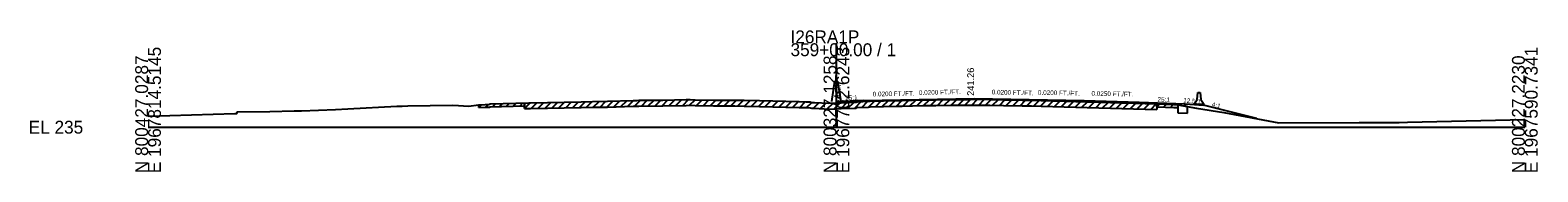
# Model space of a CAD drawing. Extents: x -26 to 304, y -10 to 7527.
# Drawn here: x -25.7 to 302.8, y 4490.3 to 4521.1 of the extents above; entities that cross this region are included whole.
import ezdxf

# ---------------------------------------------------------------- set-up
doc = ezdxf.new("R2010")
doc.units = 0
for name, color, linetype in [('Default', 7, 'Continuous'), ('RD_GPK_XS_Cell', 7, 'Continuous'), ('RD_XS_Base', 7, 'Continuous'), ('RD_XS_Box', 7, 'Continuous'), ('RD_XS_EarthShd', 7, 'Continuous'), ('RD_XS_ExGround', 7, 'Continuous'), ('RD_XS_ExPaveRet', 7, 'Continuous'), ('RD_XS_Misc_Line', 7, 'Continuous'), ('RD_XS_Pave', 7, 'Continuous'), ('RD_XS_PaveShd', 7, 'Continuous'), ('RD_XS_TX_Elev_EX', 7, 'Continuous'), ('RD_XS_TX_Elev_PR', 7, 'Continuous'), ('RD_XS_TX_Misc', 7, 'Continuous'), ('RD_XS_TX_MkPT', 7, 'Continuous'), ('RD_XS_TX_Profile', 7, 'Continuous'), ('RD_XS_TX_Station', 7, 'Continuous')]:
    doc.layers.add(name, color=color, linetype=linetype)

msp = doc.modelspace()

# ---------------------------------------------------------------- linework, layer by layer
at = {"layer": 'Default'}
for p, q in [((228.58, 4506), (228.75, 4507.58)), ((228.75, 4507.58), (229.25, 4507.58)), ((229.25, 4507.58), (229.42, 4506)), ((228, 4505.17), (228.58, 4506)), ((228, 4504.92), (228, 4505.17)), ((230, 4504.92), (228, 4504.92)), ((229.42, 4506), (230, 4505.17)), ((230, 4505.17), (230, 4504.92))]:
    msp.add_line(p, q, dxfattribs=at)
at = {"layer": 'RD_GPK_XS_Cell'}
for p, q in [((150, 4500), (150, 4518.25)), ((0, 4500), (150, 4500)), ((150, 4500), (300, 4500))]:
    msp.add_line(p, q, dxfattribs=at)
at = {"layer": 'RD_XS_Base'}
for p, q in [((150, 4505.27), (150, 4505.54)), ((226, 4504.52), (226, 4505.08)), ((226.5, 4504.5), (226, 4504.52)), ((226.5, 4503.02), (226.5, 4504.5)), ((224.41, 4503.1), (226.5, 4503.02))]:
    msp.add_line(p, q, dxfattribs=at)
at = {"layer": 'RD_XS_Box'}
msp.add_line((241.6, 4501.86), (230, 4504.76), dxfattribs=at)
at = {"layer": 'RD_XS_EarthShd'}
for p, q in [((149, 4505.56), (149.67, 4510.04)), ((150, 4510.04), (149.67, 4510.04)), ((150, 4510.04), (150.33, 4510.04)), ((151, 4505.56), (150.33, 4510.04)), ((226, 4505.08), (230, 4504.76))]:
    msp.add_line(p, q, dxfattribs=at)
at = {"layer": 'RD_XS_ExGround'}
msp.add_lwpolyline([(0, 4502.43), (18.88, 4503), (19.37, 4503.01), (19.47, 4503.31), (26.5, 4503.43), (31.84, 4503.58), (33.4, 4503.57), (40.81, 4503.82), (43.56, 4504), (54.21, 4504.56), (55.36, 4504.61), (56.58, 4504.64), (66.31, 4504.81), (67.67, 4504.71), (69.84, 4504.58), (72.06, 4504.89), (73.48, 4504.96), (74.38, 4505.01), (74.52, 4505.06), (82.97, 4505.32), (83.3, 4505.33), (94.35, 4505.54), (96.86, 4505.58), (100.1, 4505.64), (105.7, 4505.82), (106.5, 4505.84), (106.96, 4505.85), (112.14, 4505.91), (117.28, 4506), (118.14, 4506.01), (119.2, 4505.99), (123.19, 4505.91), (127.87, 4505.88), (129.87, 4505.86), (133.25, 4505.78), (141.89, 4505.56), (143.42, 4505.52), (144.26, 4505.49), (144.55, 4505.4), (145.25, 4505.39), (148.36, 4505.21), (150, 4505.27), (151.03, 4505.31), (154.33, 4505.42), (154.55, 4505.52), (157.02, 4505.64), (157.34, 4505.66), (163.19, 4505.8), (164.33, 4505.83), (168.79, 4505.96), (171.67, 4505.99), (174.88, 4506.03), (178.97, 4506.06), (181.06, 4506.08), (183.41, 4506.03), (186.38, 4505.97), (190.46, 4505.91), (192.54, 4505.88), (194.6, 4505.82), (204.6, 4505.55), (217.3, 4505.17), (223.52, 4504.91), (224.41, 4504.88), (228.48, 4504.14), (234.42, 4503.19), (246.39, 4500.97), (263.88, 4501), (272.65, 4501.01), (274.43, 4501.08), (300, 4501.71)], dxfattribs=at)
at = {"layer": 'RD_XS_ExPaveRet'}
for p, q in [((72.06, 4504.27), (72.06, 4504.89)), ((72.06, 4504.27), (73.48, 4504.34)), ((73.48, 4504.34), (74.38, 4504.38)), ((74.38, 4504.38), (74.52, 4504.43)), ((74.52, 4504.43), (82, 4504.67)), ((82, 4504.04), (82, 4505.29)), ((82, 4505.29), (82, 4504.67)), ((83.3, 4504.08), (94.35, 4504.29)), ((94.35, 4504.29), (96.86, 4504.33)), ((96.86, 4504.33), (100.1, 4504.39)), ((100.1, 4504.39), (105.7, 4504.57)), ((105.7, 4504.57), (106.5, 4504.59)), ((106.5, 4504.59), (106.96, 4504.6)), ((106.96, 4504.6), (112.14, 4504.66)), ((112.14, 4504.66), (117.28, 4504.75)), ((117.28, 4504.75), (118.14, 4504.76)), ((118.14, 4504.76), (119.2, 4504.74)), ((119.2, 4504.74), (123.19, 4504.66)), ((123.19, 4504.66), (127.87, 4504.63)), ((127.87, 4504.63), (129.87, 4504.61)), ((129.87, 4504.61), (133.25, 4504.53)), ((133.25, 4504.53), (141.89, 4504.31)), ((141.89, 4504.31), (143.42, 4504.27)), ((143.42, 4504.27), (144.26, 4504.24)), ((144.26, 4504.24), (144.55, 4504.15)), ((154.33, 4504.17), (154.55, 4504.27)), ((154.55, 4504.27), (157.02, 4504.39)), ((157.02, 4504.39), (157.34, 4504.41)), ((157.34, 4504.41), (163.19, 4504.55)), ((163.19, 4504.55), (164.33, 4504.58)), ((164.33, 4504.58), (168.79, 4504.71)), ((168.79, 4504.71), (171.67, 4504.74)), ((171.67, 4504.74), (174.88, 4504.78)), ((174.88, 4504.78), (178.97, 4504.81)), ((178.97, 4504.81), (181.06, 4504.83)), ((181.06, 4504.83), (183.41, 4504.78)), ((183.41, 4504.78), (186.38, 4504.72)), ((186.38, 4504.72), (190.46, 4504.66)), ((190.46, 4504.66), (192.54, 4504.63)), ((192.54, 4504.63), (194.6, 4504.57)), ((194.6, 4504.57), (204.6, 4504.3)), ((204.6, 4504.3), (217.3, 4503.92)), ((219.79, 4505.07), (219.79, 4503.82)), ((219.79, 4504.44), (219.79, 4505.07)), ((219.79, 4504.44), (223.52, 4504.29)), ((223.52, 4504.29), (224.41, 4504.26)), ((224.41, 4504.88), (224.41, 4504.26)), ((82, 4504.04), (82.97, 4504.07)), ((82.97, 4504.07), (83.3, 4504.08)), ((144.55, 4504.15), (145.25, 4504.14)), ((145.25, 4504.14), (148.36, 4503.96)), ((148.36, 4503.96), (150, 4504.02)), ((150, 4504.02), (151.03, 4504.06)), ((151.03, 4504.06), (154.33, 4504.17)), ((217.3, 4503.92), (219.79, 4503.82))]:
    msp.add_line(p, q, dxfattribs=at)
at = {"layer": 'RD_XS_Misc_Line'}
for p, q in [((72.06, 4504.27), (72.72, 4504.93)), ((73.56, 4504.34), (74.22, 4505)), ((75.06, 4504.45), (75.7, 4505.1)), ((76.56, 4504.5), (77.2, 4505.14)), ((78.06, 4504.54), (78.7, 4505.19)), ((79.56, 4504.59), (80.2, 4505.24)), ((81.06, 4504.64), (81.7, 4505.28)), ((82, 4504.04), (83.29, 4505.33)), ((83.5, 4504.08), (84.77, 4505.36)), ((85, 4504.11), (86.27, 4505.38)), ((86.5, 4504.14), (87.77, 4505.41)), ((88, 4504.17), (89.27, 4505.44)), ((89.5, 4504.2), (90.77, 4505.47)), ((91, 4504.22), (92.27, 4505.5)), ((92.5, 4504.25), (93.77, 4505.53)), ((94, 4504.28), (95.27, 4505.55)), ((95.5, 4504.31), (96.77, 4505.58)), ((97, 4504.34), (98.27, 4505.61)), ((98.5, 4504.36), (99.77, 4505.64)), ((100, 4504.39), (101.29, 4505.68)), ((101.5, 4504.43), (102.79, 4505.73)), ((103, 4504.48), (104.29, 4505.77)), ((104.5, 4504.53), (105.79, 4505.82)), ((106, 4504.58), (107.28, 4505.85)), ((107.5, 4504.6), (108.76, 4505.87)), ((109, 4504.62), (110.26, 4505.89)), ((110.5, 4504.64), (111.76, 4505.9)), ((112, 4504.65), (113.27, 4505.93)), ((113.5, 4504.68), (114.77, 4505.95)), ((115, 4504.71), (116.27, 4505.98)), ((116.5, 4504.74), (117.77, 4506.01)), ((118, 4504.76), (119.23, 4505.99)), ((119.5, 4504.73), (120.73, 4505.96)), ((121, 4504.7), (122.23, 4505.93)), ((122.5, 4504.67), (123.73, 4505.91)), ((124, 4504.65), (125.24, 4505.89)), ((125.5, 4504.64), (126.74, 4505.88)), ((127, 4504.63), (128.24, 4505.87)), ((128.5, 4504.62), (129.74, 4505.86)), ((130, 4504.61), (131.22, 4505.83)), ((131.5, 4504.57), (132.72, 4505.79)), ((133, 4504.53), (134.22, 4505.75)), ((134.5, 4504.5), (135.72, 4505.71)), ((136, 4504.46), (137.22, 4505.68)), ((137.5, 4504.42), (138.72, 4505.64)), ((139, 4504.38), (140.22, 4505.6)), ((140.5, 4504.34), (141.72, 4505.56)), ((142, 4504.3), (143.22, 4505.53)), ((143.5, 4504.27), (144.63, 4505.4)), ((145, 4504.14), (146.19, 4505.33)), ((146.5, 4504.06), (147.68, 4505.25)), ((148, 4503.98), (149.26, 4505.24)), ((149.5, 4504), (150.8, 4505.3)), ((151, 4504.06), (152.29, 4505.35)), ((152.5, 4504.11), (153.79, 4505.4)), ((154, 4504.16), (155.4, 4505.56)), ((155.5, 4504.31), (156.82, 4505.63)), ((157, 4504.39), (158.29, 4505.68)), ((158.5, 4504.44), (159.78, 4505.72)), ((160, 4504.47), (161.28, 4505.75)), ((161.5, 4504.51), (162.78, 4505.79)), ((163, 4504.54), (164.28, 4505.83)), ((164.5, 4504.58), (165.79, 4505.87)), ((166, 4504.63), (167.29, 4505.91)), ((167.5, 4504.67), (168.79, 4505.96)), ((169, 4504.71), (170.26, 4505.97)), ((170.5, 4504.73), (171.76, 4505.99)), ((172, 4504.74), (173.27, 4506.01)), ((173.5, 4504.76), (174.77, 4506.03)), ((175, 4504.79), (176.26, 4506.04)), ((176.5, 4504.8), (177.76, 4506.06)), ((178, 4504.81), (179.26, 4506.07)), ((179.5, 4504.82), (180.76, 4506.08)), ((181, 4504.83), (182.22, 4506.06)), ((182.5, 4504.8), (183.72, 4506.02)), ((184, 4504.77), (185.22, 4505.99)), ((185.5, 4504.74), (186.73, 4505.96)), ((187, 4504.71), (188.23, 4505.94)), ((188.5, 4504.69), (189.73, 4505.92)), ((190, 4504.66), (191.23, 4505.9)), ((191.5, 4504.64), (192.73, 4505.87)), ((193, 4504.62), (194.21, 4505.83)), ((194.5, 4504.57), (195.72, 4505.79)), ((196, 4504.53), (197.22, 4505.75)), ((197.5, 4504.49), (198.72, 4505.71)), ((199, 4504.45), (200.22, 4505.67)), ((200.5, 4504.41), (201.72, 4505.63)), ((202, 4504.37), (203.22, 4505.59)), ((203.5, 4504.33), (204.72, 4505.55)), ((205, 4504.29), (206.21, 4505.51)), ((206.5, 4504.25), (207.71, 4505.46)), ((208, 4504.2), (209.21, 4505.41)), ((209.5, 4504.16), (210.71, 4505.37)), ((211, 4504.11), (212.21, 4505.32)), ((212.5, 4504.06), (213.71, 4505.28)), ((214, 4504.02), (215.21, 4505.23)), ((215.5, 4503.97), (216.71, 4505.19)), ((217, 4503.93), (218.2, 4505.13)), ((218.5, 4503.87), (219.7, 4505.07)), ((219.79, 4504.44), (220.39, 4505.04)), ((221.29, 4504.38), (221.89, 4504.98)), ((222.79, 4504.32), (223.39, 4504.92))]:
    msp.add_line(p, q, dxfattribs=at)
at = {"layer": 'RD_XS_Pave'}
for p, q in [((156, 4505.78), (180, 4506.26)), ((180, 4506.26), (204, 4505.78)), ((204, 4505.78), (216, 4505.48))]:
    msp.add_line(p, q, dxfattribs=at)
at = {"layer": 'RD_XS_PaveShd'}
for p, q in [((156, 4505.78), (150, 4505.54)), ((216, 4505.48), (226, 4505.08))]:
    msp.add_line(p, q, dxfattribs=at)
at = {"layer": 'RD_XS_TX_Elev_PR'}
for p, q in [((150, 4505.27), (151.03, 4505.31)), ((151.03, 4505.31), (154.33, 4505.42)), ((154.33, 4505.42), (154.55, 4505.52)), ((154.55, 4505.52), (157.02, 4505.64)), ((157.02, 4505.64), (157.34, 4505.66)), ((157.34, 4505.66), (163.19, 4505.8)), ((163.19, 4505.8), (164.33, 4505.83)), ((164.33, 4505.83), (168.79, 4505.96)), ((168.79, 4505.96), (171.67, 4505.99)), ((171.67, 4505.99), (174.88, 4506.03)), ((174.88, 4506.03), (178.97, 4506.06)), ((178.97, 4506.06), (181.06, 4506.08)), ((181.06, 4506.08), (183.41, 4506.03)), ((183.41, 4506.03), (186.38, 4505.97)), ((186.38, 4505.97), (190.46, 4505.91)), ((190.46, 4505.91), (192.54, 4505.88)), ((192.54, 4505.88), (194.6, 4505.82)), ((194.6, 4505.82), (204.6, 4505.55)), ((204.6, 4505.55), (217.3, 4505.17)), ((217.3, 4505.17), (219.79, 4505.07)), ((219.79, 4505.07), (223.52, 4504.91)), ((223.52, 4504.91), (224.41, 4504.88)), ((224.41, 4504.88), (224.41, 4503.1))]:
    msp.add_line(p, q, dxfattribs=at)

# ---------------------------------------------------------------- texts
at = {"layer": 'RD_GPK_XS_Cell'}
for s, p in [('I26RA1P', (140, 4518.25)), ('359+00.00 / 1', (140, 4515.45)), ('EL 235', (-26, 4498.6))]:
    msp.add_text(s, height=2.8, dxfattribs=at).set_placement(p)
for s, p in [('E 1967814.5145', (2.8, 4490)), ('N 800427.0287', (0, 4490)), ('N 800327.1258', (150, 4490)), ('E 1967702.6243', (152.8, 4490)), ('N 800227.2230', (300, 4490)), ('E 1967590.7341', (302.8, 4490))]:
    msp.add_text(s, height=2.8, rotation=90, dxfattribs=at).set_placement(p)
at = {"layer": 'RD_XS_TX_Elev_EX'}
msp.add_text('240.27', height=1, rotation=90, dxfattribs=at).set_placement((151, 4505.27))
at = {"layer": 'RD_XS_TX_Misc'}
msp.add_text('12.5:1', height=1, rotation=355.4261, dxfattribs=at).set_placement((225.54, 4505.36))
at = {"layer": 'RD_XS_TX_MkPT'}
for rotation, p in [(2.2906, (151.94, 4505.86)), (357.7094, (219.96, 4505.57))]:
    msp.add_text('25:1', height=1, rotation=rotation, dxfattribs=at).set_placement(p)
at = {"layer": 'RD_XS_TX_Profile'}
for s, rotation, p in [('0.0200 FT./FT.', 1.1458, (157.92, 4506.7)), ('0.0200 FT./FT.', 1.1458, (167.98, 4507.02)), ('0.0200 FT./FT.', 358.5679, (183.83, 4507.16)), ('0.0200 FT./FT.', 358.8542, (193.89, 4507.06)), ('0.0250 FT./FT.', 358.8542, (205.57, 4506.86)), ('4:1', 345.9638, (231.72, 4504.54))]:
    msp.add_text(s, height=1, rotation=rotation, dxfattribs=at).set_placement(p)
at = {"layer": 'RD_XS_TX_Station'}
msp.add_text(' 241.26', height=1.5, rotation=90, dxfattribs=at).set_placement((180, 4506.26))

doc.saveas('drawing.dxf')
